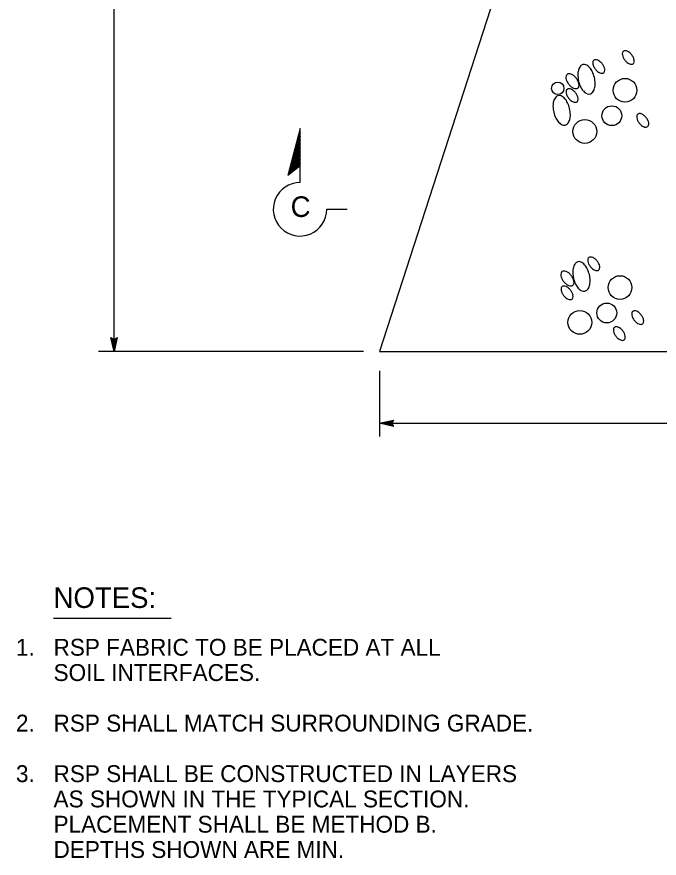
# Model space of a CAD drawing. Extents: x 6707692 to 6708868, y 1870875 to 1871658.
# Drawn here: x 6707692.4 to 6707917.2, y 1870893.1 to 1871187.6 of the extents above; entities that cross this region are included whole.
import ezdxf

# ---------------------------------------------------------------- set-up
doc = ezdxf.new("R2010")
doc.units = 0
doc.layers.add('Level 60', color=7, linetype='Continuous')

msp = doc.modelspace()

# ---------------------------------------------------------------- linework, layer by layer
at = {"layer": 'Level 60'}
for p, q in [((6707726.44, 1871070.4), (6707726.44, 1871358.74)), ((6707912.57, 1871358.74), (6707819.35, 1871070.4)), ((6707791.53, 1871148.57), (6707787.31, 1871132.01)), ((6707791.53, 1871147.21), (6707787.75, 1871132.37)), ((6707791.53, 1871129.6), (6707791.53, 1871148.57)), ((6707791.53, 1871145.85), (6707788.18, 1871132.72)), ((6707791.53, 1871144.49), (6707788.62, 1871133.07)), ((6707791.53, 1871143.13), (6707789.06, 1871133.43)), ((6707791.53, 1871141.76), (6707789.5, 1871133.78)), ((6707791.53, 1871140.4), (6707789.93, 1871134.14)), ((6707791.53, 1871139.04), (6707790.37, 1871134.49)), ((6707791.53, 1871135.43), (6707787.31, 1871132.01)), ((6707791.53, 1871137.68), (6707790.81, 1871134.85)), ((6707791.53, 1871136.32), (6707791.25, 1871135.2)), ((6707800.9, 1871120.24), (6707808.02, 1871120.24)), ((6707726.44, 1871070.4), (6707725.35, 1871075.32)), ((6707725.35, 1871075.32), (6707725.35, 1871075.32)), ((6707725.35, 1871075.32), (6707726.44, 1871074.66)), ((6707726.44, 1871071.54), (6707725.65, 1871075.12)), ((6707726.44, 1871072.66), (6707725.93, 1871074.98)), ((6707726.44, 1871073.8), (6707726.22, 1871074.79)), ((6707726.44, 1871074.66), (6707727.54, 1871075.32)), ((6707727.54, 1871075.32), (6707726.44, 1871070.4)), ((6707727.25, 1871075.14), (6707726.44, 1871071.53)), ((6707726.95, 1871074.95), (6707726.44, 1871072.66)), ((6707726.67, 1871074.8), (6707726.44, 1871073.8)), ((6707727.54, 1871075.32), (6707727.54, 1871075.32)), ((6707813.76, 1871070.4), (6707721.02, 1871070.4)), ((6707726.44, 1871070.4), (6707726.44, 1871072.2)), ((6707726.44, 1871070.4), (6707726.44, 1871070.4)), ((6707819.35, 1871063.62), (6707819.35, 1871040.71)), ((6707819.35, 1871045.32), (6707824.27, 1871046.41)), ((6707819.35, 1871045.32), (6708097.63, 1871045.32)), ((6707819.35, 1871045.32), (6707821.15, 1871045.32)), ((6707824.27, 1871044.22), (6707819.35, 1871045.32)), ((6707819.35, 1871045.32), (6707819.35, 1871045.32)), ((6707824.09, 1871044.51), (6707820.48, 1871045.32)), ((6707820.49, 1871045.32), (6707824.07, 1871046.11)), ((6707821.61, 1871045.32), (6707823.93, 1871045.83)), ((6707823.9, 1871044.81), (6707821.61, 1871045.32)), ((6707822.75, 1871045.31), (6707823.74, 1871045.53)), ((6707823.75, 1871045.09), (6707822.75, 1871045.31)), ((6707824.27, 1871046.41), (6707823.61, 1871045.32)), ((6707823.61, 1871045.32), (6707824.27, 1871044.22)), ((6707824.27, 1871046.41), (6707824.27, 1871046.41)), ((6707824.27, 1871044.22), (6707824.27, 1871044.22)), ((6707705.28, 1870977.05), (6707746.46, 1870977.05))]:
    msp.add_line(p, q, dxfattribs=at)
msp.add_lwpolyline([(6707819.35, 1871070.4), (6708097.63, 1871070.4)], dxfattribs=at)
for centre, radius in [((6707881.76, 1871162.57), 2.16), ((6707905.27, 1871161.89), 4.16), ((6707900.66, 1871152.99), 3.47), ((6707891.21, 1871147.47), 4.16), ((6707903.52, 1871092.83), 4.16), ((6707898.9, 1871083.93), 3.47), ((6707889.46, 1871080.64), 4.16)]:
    msp.add_circle(centre, radius, dxfattribs=at)
for centre, radius, start, end in [((6707906.34, 1871174.58), 2.01, 165.2987, 189.5193), ((6707907.56, 1871174.79), 3.25, 189.5193, 205.5514), ((6707905.25, 1871174.87), 0.886, 128.4436, 165.2987), ((6707909.15, 1871175.55), 5.01, 205.5514, 218.4436), ((6707905.25, 1871174.87), 0.886, 91.5884, 128.4436), ((6707905.28, 1871173.74), 2.01, 67.3678, 91.5884), ((6707904.8, 1871172.6), 3.25, 51.3357, 67.3678), ((6707903.7, 1871171.22), 5.01, 38.4436, 51.3357), ((6707903.7, 1871171.22), 5.01, 25.5514, 38.4436), ((6707905.29, 1871171.98), 3.25, 9.5193, 25.5514), ((6707890.94, 1871169.35), 1.61, 103.3223, 140.9226), ((6707890.94, 1871169.35), 1.61, 65.722, 103.3223), ((6707890.03, 1871167.33), 3.82, 41.5964, 65.722), ((6707896, 1871171.41), 2.01, 165.2987, 189.5193), ((6707897.22, 1871171.61), 3.25, 189.5193, 205.5514), ((6707894.92, 1871171.69), 0.886, 128.4436, 165.2987), ((6707894.92, 1871171.69), 0.886, 91.5884, 128.4436), ((6707894.95, 1871170.57), 2.01, 67.3678, 91.5884), ((6707894.47, 1871169.43), 3.25, 51.3357, 67.3678), ((6707893.37, 1871168.05), 5.01, 38.4436, 51.3357), ((6707893.37, 1871168.05), 5.01, 25.5514, 38.4436), ((6707909.15, 1871175.55), 5.01, 218.4436, 231.3357), ((6707908.05, 1871174.17), 3.25, 231.3357, 247.3678), ((6707907.57, 1871173.03), 2.01, 247.3678, 271.5884), ((6707907.6, 1871171.9), 0.886, 271.5884, 308.4436), ((6707907.6, 1871171.9), 0.886, 308.4436, 345.2987), ((6707906.51, 1871172.19), 2.01, 345.2987, 9.5193), ((6707885.59, 1871166.7), 0.975, 91.5884, 128.4436), ((6707885.62, 1871165.46), 2.21, 67.3678, 91.5884), ((6707885.1, 1871164.21), 3.57, 51.3357, 67.3678), ((6707895.04, 1871167.32), 6.29, 165.0482, 180.7625), ((6707892.66, 1871167.95), 3.82, 140.9226, 165.0482), ((6707888.18, 1871165.69), 6.29, 25.8821, 41.5964), ((6707885, 1871164.15), 9.82, 13.3223, 25.8821), ((6707898.82, 1871172.37), 5.01, 205.5514, 218.4436), ((6707898.82, 1871172.37), 5.01, 218.4436, 231.3357), ((6707897.71, 1871171), 3.25, 231.3357, 247.3678), ((6707897.24, 1871169.85), 2.01, 247.3678, 271.5884), ((6707897.27, 1871168.73), 0.886, 271.5884, 308.4436), ((6707897.27, 1871168.73), 0.886, 308.4436, 345.2987), ((6707894.96, 1871168.81), 3.25, 9.5193, 25.5514), ((6707896.18, 1871169.01), 2.01, 345.2987, 9.5193), ((6707886.78, 1871166.39), 2.21, 165.2987, 189.5193), ((6707888.13, 1871166.61), 3.57, 189.5193, 205.5514), ((6707885.59, 1871166.7), 0.975, 128.4436, 165.2987), ((6707889.88, 1871167.45), 5.51, 205.5514, 218.4436), ((6707883.88, 1871162.69), 5.51, 38.4436, 51.3357), ((6707883.88, 1871162.69), 5.51, 25.5514, 38.4436), ((6707898.57, 1871167.36), 9.82, 180.7625, 193.3223), ((6707885.63, 1871163.53), 3.57, 9.5193, 25.5514), ((6707898.57, 1871167.36), 9.82, 193.3223, 205.8821), ((6707885, 1871164.15), 9.82, 0.7625, 13.3223), ((6707886.67, 1871161.25), 2.01, 165.2987, 189.5193), ((6707885.58, 1871161.53), 0.886, 128.4436, 165.2987), ((6707885.58, 1871161.53), 0.886, 91.5884, 128.4436), ((6707889.88, 1871167.45), 5.51, 218.4436, 231.3357), ((6707885.61, 1871160.41), 2.01, 67.3678, 91.5884), ((6707885.14, 1871159.26), 3.25, 51.3357, 67.3678), ((6707888.66, 1871165.93), 3.57, 231.3357, 247.3678), ((6707884.04, 1871157.89), 5.01, 38.4436, 51.3357), ((6707888.14, 1871164.68), 2.21, 247.3678, 271.5884), ((6707888.17, 1871163.44), 0.975, 271.5884, 308.4436), ((6707888.17, 1871163.44), 0.975, 308.4436, 345.2987), ((6707886.98, 1871163.75), 2.21, 345.2987, 9.5193), ((6707895.39, 1871165.82), 6.29, 205.8821, 221.5964), ((6707893.55, 1871164.19), 3.82, 221.5964, 245.722), ((6707890.92, 1871163.56), 3.82, 320.9226, 345.0482), ((6707888.54, 1871164.2), 6.29, 345.0482, 0.7625), ((6707883.98, 1871157.03), 3.82, 140.9226, 165.0482), ((6707882.26, 1871158.43), 1.61, 103.3223, 140.9226), ((6707882.26, 1871158.43), 1.61, 65.722, 103.3223), ((6707881.35, 1871156.41), 3.82, 41.5964, 65.722), ((6707879.51, 1871154.77), 6.29, 25.8821, 41.5964), ((6707887.89, 1871161.45), 3.25, 189.5193, 205.5514), ((6707889.48, 1871162.21), 5.01, 205.5514, 218.4436), ((6707889.48, 1871162.21), 5.01, 218.4436, 231.3357), ((6707884.04, 1871157.89), 5.01, 25.5514, 38.4436), ((6707885.63, 1871158.65), 3.25, 9.5193, 25.5514), ((6707886.85, 1871158.85), 2.01, 345.2987, 9.5193), ((6707892.64, 1871162.17), 1.61, 245.722, 283.3223), ((6707892.64, 1871162.17), 1.61, 283.3223, 320.9226), ((6707886.36, 1871156.4), 6.29, 165.0482, 180.7625), ((6707889.89, 1871156.44), 9.82, 180.7625, 193.3223), ((6707876.33, 1871153.23), 9.82, 13.3223, 25.8821), ((6707888.38, 1871160.83), 3.25, 231.3357, 247.3678), ((6707887.9, 1871159.69), 2.01, 247.3678, 271.5884), ((6707887.94, 1871158.57), 0.886, 271.5884, 308.4436), ((6707887.94, 1871158.57), 0.886, 308.4436, 345.2987), ((6707889.89, 1871156.44), 9.82, 193.3223, 205.8821), ((6707876.33, 1871153.23), 9.82, 0.7625, 13.3223), ((6707879.86, 1871153.28), 6.29, 345.0482, 0.7625), ((6707911.4, 1871152.57), 2.01, 165.2987, 189.5193), ((6707910.31, 1871152.85), 0.886, 128.4436, 165.2987), ((6707910.31, 1871152.85), 0.886, 91.5884, 128.4436), ((6707910.34, 1871151.73), 2.01, 67.3678, 91.5884), ((6707909.87, 1871150.58), 3.25, 51.3357, 67.3678), ((6707908.76, 1871149.21), 5.01, 38.4436, 51.3357), ((6707886.72, 1871154.9), 6.29, 205.8821, 221.5964), ((6707884.87, 1871153.27), 3.82, 221.5964, 245.722), ((6707883.96, 1871151.25), 1.61, 283.3223, 320.9226), ((6707882.24, 1871152.64), 3.82, 320.9226, 345.0482), ((6707912.62, 1871152.77), 3.25, 189.5193, 205.5514), ((6707914.21, 1871153.53), 5.01, 205.5514, 218.4436), ((6707914.21, 1871153.53), 5.01, 218.4436, 231.3357), ((6707908.76, 1871149.21), 5.01, 25.5514, 38.4436), ((6707910.36, 1871149.97), 3.25, 9.5193, 25.5514), ((6707911.58, 1871150.17), 2.01, 345.2987, 9.5193), ((6707883.96, 1871151.25), 1.61, 245.722, 283.3223), ((6707913.11, 1871152.15), 3.25, 231.3357, 247.3678), ((6707912.63, 1871151.01), 2.01, 247.3678, 271.5884), ((6707912.66, 1871149.89), 0.886, 271.5884, 308.4436), ((6707912.66, 1871149.89), 0.886, 308.4436, 345.2987), ((6707791.53, 1871120.23), 9.37, 90, 0.0005), ((6707894.25, 1871102.35), 2.01, 165.2987, 189.5193), ((6707893.16, 1871102.63), 0.886, 128.4436, 165.2987), ((6707893.16, 1871102.63), 0.886, 91.5884, 128.4436), ((6707893.19, 1871101.51), 2.01, 67.3678, 91.5884), ((6707892.72, 1871100.36), 3.25, 51.3357, 67.3678), ((6707891.62, 1871098.99), 5.01, 38.4436, 51.3357), ((6707893.28, 1871098.26), 6.29, 165.0482, 180.7625), ((6707890.9, 1871098.89), 3.82, 140.9226, 165.0482), ((6707889.18, 1871100.29), 1.61, 103.3223, 140.9226), ((6707889.18, 1871100.29), 1.61, 65.722, 103.3223), ((6707888.27, 1871098.27), 3.82, 41.5964, 65.722), ((6707886.43, 1871096.63), 6.29, 25.8821, 41.5964), ((6707895.47, 1871102.55), 3.25, 189.5193, 205.5514), ((6707897.06, 1871103.31), 5.01, 205.5514, 218.4436), ((6707897.06, 1871103.31), 5.01, 218.4436, 231.3357), ((6707891.62, 1871098.99), 5.01, 25.5514, 38.4436), ((6707893.21, 1871099.75), 3.25, 9.5193, 25.5514), ((6707894.43, 1871099.95), 2.01, 345.2987, 9.5193), ((6707885.03, 1871097.32), 2.21, 165.2987, 189.5193), ((6707886.37, 1871097.55), 3.57, 189.5193, 205.5514), ((6707883.83, 1871097.64), 0.975, 128.4436, 165.2987), ((6707883.83, 1871097.64), 0.975, 91.5884, 128.4436), ((6707883.87, 1871096.4), 2.21, 67.3678, 91.5884), ((6707883.34, 1871095.14), 3.57, 51.3357, 67.3678), ((6707882.13, 1871093.63), 5.51, 38.4436, 51.3357), ((6707882.13, 1871093.63), 5.51, 25.5514, 38.4436), ((6707896.82, 1871098.3), 9.82, 180.7625, 193.3223), ((6707883.25, 1871095.09), 9.82, 13.3223, 25.8821), ((6707883.25, 1871095.09), 9.82, 0.7625, 13.3223), ((6707895.96, 1871101.93), 3.25, 231.3357, 247.3678), ((6707895.49, 1871100.79), 2.01, 247.3678, 271.5884), ((6707895.52, 1871099.67), 0.886, 271.5884, 308.4436), ((6707895.52, 1871099.67), 0.886, 308.4436, 345.2987), ((6707888.12, 1871098.39), 5.51, 205.5514, 218.4436), ((6707888.12, 1871098.39), 5.51, 218.4436, 231.3357), ((6707886.91, 1871096.87), 3.57, 231.3357, 247.3678), ((6707886.42, 1871094.38), 0.975, 308.4436, 345.2987), ((6707883.88, 1871094.47), 3.57, 9.5193, 25.5514), ((6707896.82, 1871098.3), 9.82, 193.3223, 205.8821), ((6707885.22, 1871094.69), 2.21, 345.2987, 9.5193), ((6707893.64, 1871096.76), 6.29, 205.8821, 221.5964), ((6707886.78, 1871095.14), 6.29, 345.0482, 0.7625), ((6707884.92, 1871092.18), 2.01, 165.2987, 189.5193), ((6707886.14, 1871092.39), 3.25, 189.5193, 205.5514), ((6707883.83, 1871092.47), 0.886, 128.4436, 165.2987), ((6707887.73, 1871093.15), 5.01, 205.5514, 218.4436), ((6707883.83, 1871092.47), 0.886, 91.5884, 128.4436), ((6707883.86, 1871091.34), 2.01, 67.3678, 91.5884), ((6707883.38, 1871090.2), 3.25, 51.3357, 67.3678), ((6707882.28, 1871088.82), 5.01, 38.4436, 51.3357), ((6707886.39, 1871095.62), 2.21, 247.3678, 271.5884), ((6707882.28, 1871088.82), 5.01, 25.5514, 38.4436), ((6707886.42, 1871094.38), 0.975, 271.5884, 308.4436), ((6707883.87, 1871089.59), 3.25, 9.5193, 25.5514), ((6707891.79, 1871095.12), 3.82, 221.5964, 245.722), ((6707890.88, 1871093.11), 1.61, 245.722, 283.3223), ((6707890.88, 1871093.11), 1.61, 283.3223, 320.9226), ((6707889.16, 1871094.5), 3.82, 320.9226, 345.0482), ((6707887.73, 1871093.15), 5.01, 218.4436, 231.3357), ((6707886.63, 1871091.77), 3.25, 231.3357, 247.3678), ((6707886.15, 1871090.63), 2.01, 247.3678, 271.5884), ((6707886.18, 1871089.5), 0.886, 271.5884, 308.4436), ((6707886.18, 1871089.5), 0.886, 308.4436, 345.2987), ((6707885.09, 1871089.79), 2.01, 345.2987, 9.5193), ((6707909.65, 1871083.5), 2.01, 165.2987, 189.5193), ((6707910.87, 1871083.71), 3.25, 189.5193, 205.5514), ((6707908.56, 1871083.79), 0.886, 128.4436, 165.2987), ((6707912.46, 1871084.47), 5.01, 205.5514, 218.4436), ((6707908.56, 1871083.79), 0.886, 91.5884, 128.4436), ((6707908.59, 1871082.66), 2.01, 67.3678, 91.5884), ((6707908.11, 1871081.52), 3.25, 51.3357, 67.3678), ((6707907.01, 1871080.15), 5.01, 38.4436, 51.3357), ((6707907.01, 1871080.15), 5.01, 25.5514, 38.4436), ((6707908.6, 1871080.91), 3.25, 9.5193, 25.5514), ((6707912.46, 1871084.47), 5.01, 218.4436, 231.3357), ((6707911.36, 1871083.09), 3.25, 231.3357, 247.3678), ((6707910.88, 1871081.95), 2.01, 247.3678, 271.5884), ((6707910.91, 1871080.82), 0.886, 271.5884, 308.4436), ((6707910.91, 1871080.82), 0.886, 308.4436, 345.2987), ((6707909.82, 1871081.11), 2.01, 345.2987, 9.5193), ((6707903.2, 1871077.91), 2.01, 165.2987, 189.5193), ((6707904.42, 1871078.12), 3.25, 189.5193, 205.5514), ((6707902.11, 1871078.2), 0.886, 128.4436, 165.2987), ((6707906.01, 1871078.88), 5.01, 205.5514, 218.4436), ((6707902.11, 1871078.2), 0.886, 91.5884, 128.4436), ((6707902.14, 1871077.07), 2.01, 67.3678, 91.5884), ((6707901.67, 1871075.93), 3.25, 51.3357, 67.3678), ((6707900.57, 1871074.56), 5.01, 38.4436, 51.3357), ((6707900.57, 1871074.56), 5.01, 25.5514, 38.4436), ((6707902.16, 1871075.32), 3.25, 9.5193, 25.5514), ((6707906.01, 1871078.88), 5.01, 218.4436, 231.3357), ((6707904.91, 1871077.5), 3.25, 231.3357, 247.3678), ((6707904.43, 1871076.36), 2.01, 247.3678, 271.5884), ((6707904.47, 1871075.24), 0.886, 271.5884, 308.4436), ((6707904.47, 1871075.24), 0.886, 308.4436, 345.2987), ((6707903.38, 1871075.52), 2.01, 345.2987, 9.5193)]:
    msp.add_arc(centre, radius, start, end, dxfattribs=at)

# ---------------------------------------------------------------- texts
for s, height, p in [('C', 7.21, (6707788.26, 1871117.55)), ('RSP FABRIC TO BE PLACED AT ALL', 5.9, (6707705.28, 1870963.94)), ('SOIL INTERFACES.', 5.9, (6707705.28, 1870955.09)), ('RSP SHALL MATCH SURROUNDING GRADE.', 5.9, (6707705.28, 1870937.39)), ('RSP SHALL BE CONSTRUCTED IN LAYERS', 5.9, (6707705.28, 1870919.69)), ('AS SHOWN IN THE TYPICAL SECTION.', 5.9, (6707705.28, 1870910.84)), ('PLACEMENT SHALL BE METHOD B.', 5.9, (6707705.28, 1870901.99)), ('DEPTHS SHOWN ARE MIN.', 5.9, (6707705.28, 1870893.14))]:
    msp.add_text(s, height=height, dxfattribs=at).set_placement(p)
for s, height, p in [('NOTES:', 7.211, (6707705.28, 1870980.66)), ('1. ', 5.9, (6707692.12, 1870963.94)), ('2. ', 5.9, (6707692.12, 1870937.39)), ('3. ', 5.9, (6707692.12, 1870919.69))]:
    msp.add_text(s, height=height, rotation=359.9999, dxfattribs=at).set_placement(p)

doc.saveas('drawing.dxf')
